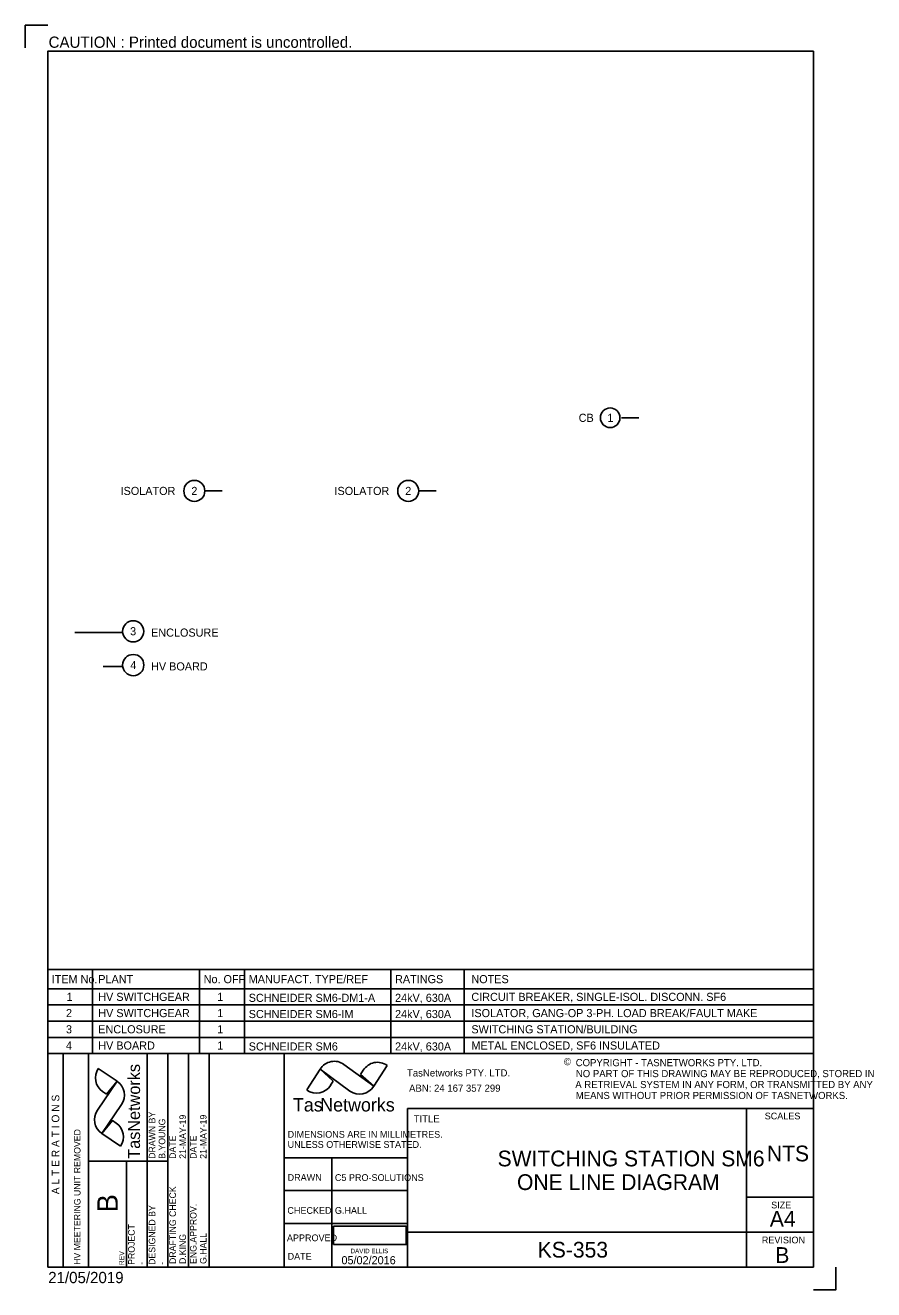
# Model space of a CAD drawing. Extents: x -195 to -7, y 8 to 289.
import ezdxf

# ---------------------------------------------------------------- set-up
doc = ezdxf.new("R2010")
doc.units = 0
for name, color, linetype in [('A4 BORDER TITLE BLOCK', 7, 'Continuous'), ('Default', 7, 'Continuous'), ('DRAWING', 7, 'Continuous'), ('REV_BLOCK', 7, 'Continuous')]:
    doc.layers.add(name, color=color, linetype=linetype)

# ---------------------------------------------------------------- blocks, each defined once
blk = doc.blocks.new('POINT_DISPLAY')
at = {"layer": 'Default'}
blk.add_line((0, 0), (0, 0), dxfattribs=at)
blk = doc.blocks.new('David Ellis')
at = {"layer": 'Default'}
blk.add_lwpolyline([(0.38, 5.03), (16.52, 5.03), (16.52, 9.1), (0.38, 9.1)], close=True, dxfattribs=at)
for s, height, p in [('DAVID ELLIS', 1, (4.15, 3.1)), ('05/02/2016', 1.8, (2.12, 0.65))]:
    blk.add_text(s, height=height, dxfattribs=at).set_placement(p)

msp = doc.modelspace()

# ---------------------------------------------------------------- linework, layer by layer
at = {"layer": 'A4 BORDER TITLE BLOCK'}
for p, q in [((-20, 60.93), (-190, 60.93)), ((-186.58, 13.5), (-186.58, 60.93)), ((-137.52, 13.5), (-137.52, 60.93)), ((-129.55, 57.45), (-132.49, 52.85)), ((-129.55, 57.45), (-132.49, 52.85)), ((-129.55, 57.45), (-132.49, 52.85)), ((-129.55, 57.45), (-122.9, 52.62)), ((-129.55, 57.45), (-126.61, 54.82)), ((-126.61, 54.82), (-129.55, 57.45)), ((-129.55, 57.45), (-122.9, 52.62)), ((-129.55, 57.45), (-122.9, 52.62)), ((-129.55, 57.45), (-126.61, 54.82)), ((-117.6, 53.69), (-124.25, 58.52)), ((-117.6, 53.69), (-124.25, 58.52)), ((-117.6, 53.69), (-124.25, 58.52)), ((-119.95, 57.22), (-120.53, 56.32)), ((-119.95, 57.22), (-120.53, 56.32)), ((-119.95, 57.22), (-120.53, 56.32)), ((-120.53, 56.32), (-117.6, 53.69)), ((-120.53, 56.32), (-117.6, 53.69)), ((-120.53, 56.32), (-117.6, 53.69)), ((-117.6, 53.69), (-114.66, 58.29)), ((-117.6, 53.69), (-114.66, 58.29)), ((-117.6, 53.69), (-114.66, 58.29)), ((-127.19, 53.92), (-126.61, 54.82)), ((-127.19, 53.92), (-126.61, 54.82)), ((-127.19, 53.92), (-126.61, 54.82)), ((-110.13, 48.77), (-20, 48.77)), ((-110.13, 48.77), (-110.13, 13.5)), ((-34.83, 13.5), (-34.83, 48.77)), ((-137.52, 37.82), (-110.13, 37.82)), ((-126.91, 37.82), (-126.91, 13.5)), ((-137.52, 30.53), (-110.13, 30.53)), ((-34.83, 29.02), (-20, 29.02)), ((-137.52, 23.23), (-110.13, 23.23)), ((-34.83, 21.26), (-110.13, 21.26)), ((-34.83, 21.26), (-20, 21.26)), ((-20, 13.5), (-190, 13.5))]:
    msp.add_line(p, q, dxfattribs=at)
msp.add_lwpolyline([(-190, 13.5), (-190, 283.5), (-20, 283.5), (-20, 13.5)], dxfattribs=at)
for centre, start_param, end_param in [((-126.39, 55.16), 5.685005, 7.255802), ((-126.39, 55.16), 5.685005, 7.255802), ((-126.39, 55.16), 5.685005, 7.255802), ((-116.8, 54.93), 5.685005, 7.255802), ((-116.8, 54.93), 5.685005, 7.255802), ((-116.8, 54.93), 5.685005, 7.255802), ((-130.34, 56.21), 2.543413, 4.114209), ((-130.34, 56.21), 2.543413, 4.114209), ((-130.34, 56.21), 2.543413, 4.114209), ((-120.75, 55.98), 2.543413, 4.114209), ((-120.75, 55.98), 2.543413, 4.114209), ((-120.75, 55.98), 2.543413, 4.114209)]:
    msp.add_ellipse(centre, major_axis=(0, 4.07), ratio=0.938106, start_param=start_param, end_param=end_param, dxfattribs=at)
at = {"layer": 'Default'}
for p, q in [((-58.75, 202.13), (-62.62, 202.13)), ((-151.25, 185.88), (-155.12, 185.88)), ((-103.75, 185.88), (-107.62, 185.88)), ((-173.4, 154.42), (-183.98, 154.42)), ((-173.4, 146.92), (-177.73, 146.92)), ((-180.05, 79.62), (-180.05, 60.93)), ((-156.3, 79.62), (-156.3, 60.93)), ((-146.3, 79.62), (-146.3, 60.93)), ((-113.8, 79.62), (-113.8, 60.93)), ((-97.55, 79.62), (-97.55, 60.93))]:
    msp.add_line(p, q, dxfattribs=at)
for points in [[(-195, 284.28), (-195, 289.28), (-190, 289.28)], [(-20, 8.5), (-15, 8.5), (-15, 13.5)]]:
    msp.add_lwpolyline(points, dxfattribs=at)
for centre, radius in [((-65.12, 202.13), 2.18), ((-157.46, 185.88), 2.34), ((-109.96, 185.88), 2.34), ((-171.04, 154.7), 2.35), ((-171.03, 147.2), 2.36)]:
    msp.add_circle(centre, radius, dxfattribs=at)
at = {"layer": 'DRAWING'}
for p, q in [((-190, 79.62), (-20, 79.62)), ((-190, 75.33), (-20, 75.33)), ((-190, 71.73), (-20, 71.73)), ((-190, 68.13), (-20, 68.13)), ((-190, 68.13), (-20, 68.13)), ((-190, 64.53), (-20, 64.53)), ((-190, 60.93), (-20, 60.93))]:
    msp.add_line(p, q, dxfattribs=at)
at = {"layer": 'REV_BLOCK'}
for p, q in [((-180.94, 13.5), (-180.94, 60.93)), ((-167.92, 13.5), (-167.92, 60.93)), ((-163.34, 13.5), (-163.34, 60.93)), ((-158.76, 13.5), (-158.76, 60.93)), ((-154.18, 13.5), (-154.18, 60.93)), ((-174.61, 54.78), (-178.79, 57.62)), ((-174.61, 54.78), (-179, 48.34)), ((-177, 51.93), (-174.61, 54.78)), ((-177.82, 52.49), (-177, 51.93)), ((-178.03, 43.21), (-173.64, 49.65)), ((-178.03, 43.21), (-175.64, 46.05)), ((-174.82, 45.49), (-175.64, 46.05)), ((-178.03, 43.21), (-173.85, 40.36)), ((-163.34, 37.05), (-180.94, 37.05)), ((-172.5, 13.5), (-172.5, 37.05))]:
    msp.add_line(p, q, dxfattribs=at)
for points in [[(-177.82, 52.49), (-177, 51.93), (-174.61, 54.78), (-178.79, 57.62)], [(-174.61, 54.78), (-179, 48.34)], [(-178.03, 43.21), (-173.64, 49.65)], [(-174.82, 45.49), (-175.64, 46.05), (-178.03, 43.21)], [(-178.03, 43.21), (-173.85, 40.36)]]:
    msp.add_lwpolyline(points, dxfattribs=at)
for centre, start, end in [((-175.74, 55.54), 145.7268, 235.7268), ((-175.74, 55.54), 145.7268, 235.7268), ((-176.69, 51.72), 325.7268, 55.7268), ((-176.69, 51.72), 325.7268, 55.7268), ((-175.95, 46.26), 145.7268, 235.7268), ((-175.95, 46.26), 145.7268, 235.7268), ((-176.9, 42.44), 325.7268, 55.7268), ((-176.9, 42.44), 325.7268, 55.7268)]:
    msp.add_arc(centre, 3.69, start, end, dxfattribs=at)

# ---------------------------------------------------------------- block references
at = {"layer": 'A4 BORDER TITLE BLOCK', "xscale": 1.7000000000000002, "yscale": 1.5882352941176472}
msp.add_blockref('POINT_DISPLAY', (-132.03, 52.53), dxfattribs=at)
msp.add_blockref('POINT_DISPLAY', (-132.03, 52.53), dxfattribs=at)
at = {"layer": 'Default'}
msp.add_blockref('David Ellis', (-126.91, 13.5), dxfattribs=at)

# ---------------------------------------------------------------- texts
at = {"layer": 'A4 BORDER TITLE BLOCK'}
for s, height, p in [('CAUTION : Printed document is uncontrolled.', 2.5, (-189.82, 284.28)), ('©', 1.59, (-75.39, 58.35)), ('COPYRIGHT - TASNETWORKS PTY. LTD.', 1.5882, (-72.78, 58.13)), ('TasNetworks PTY. LTD.', 1.5882, (-110.24, 55.85)), ('NO PART OF THIS DRAWING MAY BE REPRODUCED, STORED IN', 1.5882, (-72.74, 55.7)), ('ABN: 24 167 357 299', 1.5882, (-109.78, 52.46)), ('A RETRIEVAL SYSTEM IN ANY FORM, OR TRANSMITTED BY ANY', 1.5882, (-72.87, 53.27)), ('Tas', 2.97, (-135.57, 48.08)), ('Networks', 2.97, (-129.51, 48.08)), ('MEANS WITHOUT PRIOR PERMISSION OF TASNETWORKS.', 1.5882, (-72.76, 50.84)), ('SCALES', 1.5, (-30.8, 46.32)), ('TITLE', 1.588, (-108.75, 45.66)), ('DIMENSIONS ARE IN MILLIMETRES.', 1.5, (-136.75, 42.25)), ('UNLESS OTHERWISE STATED.', 1.5, (-136.75, 40)), ('SWITCHING STATION SM6', 3.5, (-90.12, 35.89)), ('NTS', 3.5, (-30.32, 37)), ('DRAWN', 1.5, (-136.75, 32.68)), ('C5 PRO-SOLUTIONS', 1.5, (-126.25, 32.65)), ('ONE LINE DIAGRAM', 3.5, (-85.81, 30.64)), ('CHECKED', 1.5, (-136.8, 25.35)), ('G.HALL', 1.5, (-126.25, 25.35)), ('A4 ', 3.5, (-29.67, 22.51)), ('SIZE', 1.5, (-29.37, 26.55)), ('APPROVED', 1.5, (-136.9, 19.27)), ('REVISION', 1.5, (-31.44, 18.79)), ('KS-353', 3.5, (-81.21, 15.63)), ('B', 3.5, (-28.45, 14.45)), ('DATE', 1.5, (-136.75, 15.16)), ('21/05/2019', 2.5, (-189.91, 9.96))]:
    msp.add_text(s, height=height, dxfattribs=at).set_placement(p)
msp.add_text('A L T E R A T I O N S', height=1.7, rotation=90, dxfattribs=at).set_placement((-187.44, 29.7))
at = {"layer": 'Default'}
for s, p in [('1', (-65.73, 201.22)), ('2', (-158.13, 184.98)), ('2', (-110.63, 184.98)), ('3', (-171.73, 153.82)), ('4', (-171.68, 146.3))]:
    msp.add_text(s, height=1.8, dxfattribs=at).set_placement(p)
at = {"layer": 'DRAWING'}
for s, p in [('CB', (-72.11, 201.22)), ('ISOLATOR', (-173.84, 184.98)), ('ISOLATOR', (-126.34, 184.98)), ('ENCLOSURE', (-167.07, 153.52)), ('HV BOARD', (-167.07, 146.02)), ('ITEM No.', (-189.14, 76.57)), ('PLANT', (-178.8, 76.57)), ('No. OFF', (-155.39, 76.57)), ('MANUFACT. TYPE/REF', (-145.39, 76.57)), ('RATINGS', (-112.89, 76.57)), ('NOTES', (-95.94, 76.57)), ('1', (-185.83, 72.63)), ('HV SWITCHGEAR', (-178.8, 72.63)), ('1', (-152.36, 72.63)), ('SCHNEIDER SM6-DM1-A', (-145.39, 72.42)), ('24kV, 630A', (-112.89, 72.42)), ('CIRCUIT BREAKER, SINGLE-ISOL. DISCONN. SF6', (-95.94, 72.63)), ('2', (-185.96, 69.03)), ('HV SWITCHGEAR', (-178.8, 69.03)), ('1', (-152.36, 69.03)), ('SCHNEIDER SM6-IM', (-145.39, 68.82)), ('24kV, 630A', (-112.89, 68.82)), ('ISOLATOR, GANG-OP 3-PH. LOAD BREAK/FAULT MAKE', (-95.94, 69.03)), ('3', (-185.97, 65.43)), ('ENCLOSURE', (-178.8, 65.43)), ('1', (-152.36, 65.43)), ('SWITCHING STATION/BUILDING', (-95.94, 65.43)), ('4', (-185.97, 61.83)), ('HV BOARD', (-178.8, 61.83)), ('1', (-152.36, 61.83)), ('SCHNEIDER SM6', (-145.39, 61.62)), ('24kV, 630A', (-112.89, 61.62)), ('METAL ENCLOSED, SF6 INSULATED', (-95.94, 61.83))]:
    msp.add_text(s, height=1.8, dxfattribs=at).set_placement(p)
at = {"layer": 'REV_BLOCK'}
for s, height, p in [('TasNetworks', 2.697, (-169.52, 37.58)), ('DRAWN BY', 1.449, (-166.13, 37.57)), ('B.YOUNG', 1.449, (-163.92, 37.57)), ('21-MAY-19', 1.449, (-159.34, 37.57)), ('21-MAY-19', 1.449, (-154.76, 37.57)), ('HV MEETERING UNIT REMOVED', 1.4491, (-182.74, 14.02)), ('DATE', 1.449, (-161.55, 37.57)), ('DATE', 1.449, (-156.97, 37.57)), ('DRAFTING CHECK', 1.4491, (-161.55, 14.22)), ('B', 4.54, (-174.47, 25.67)), ('DESIGNED BY', 1.4491, (-166.13, 14.02)), ('ENG.APPROV.', 1.4491, (-156.97, 14.22)), ('PROJECT', 1.449, (-170.71, 14.02)), ('D.KING', 1.449, (-159.34, 14.22)), ('G.HALL', 1.449, (-154.76, 14.22)), ('REV', 1.117, (-173.03, 13.9)), ('-', 1.45, (-168.5, 14.02)), ('-', 1.45, (-163.91, 14.02))]:
    msp.add_text(s, height=height, rotation=90, dxfattribs=at).set_placement(p)

doc.saveas('drawing.dxf')
